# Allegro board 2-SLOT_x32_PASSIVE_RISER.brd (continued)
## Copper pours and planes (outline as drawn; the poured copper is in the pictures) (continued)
GND_A on L2_GND (solid shape): outline of 148 points within -9.4,0.76 159.4,195
GND_A on L4_PWR (solid shape): outline of 148 points within -9.4,0.76 159.4,195
GND_A on L5_PWR (solid shape): outline of 148 points within -9.4,0.76 159.4,195
GND_A on L7_GND (solid shape): outline of 148 points within -9.4,0.76 159.4,195
GND_D on L2_GND: -8.64,337.95 -9.02,338.06 -9.3,338.34 -9.34,338.41 -9.38,338.56 -9.4,338.71 -9.4,348.62 -9.17,349.16 -8.64,349.38 199.14,349.38 199.67,349.16 199.9,348.62 199.9,338.71 199.67,338.17 199.14,337.95 ; 8 cut-outs
GND_D on L4_PWR, L5_PWR: -8.64,337.95 -9.02,338.06 -9.3,338.34 -9.34,338.41 -9.38,338.56 -9.4,338.71 -9.4,348.62 -9.17,349.16 -8.64,349.38 199.14,349.38 199.67,349.16 199.9,348.62 199.9,338.71 199.67,338.17 199.14,337.95
GND_D on L7_GND: -8.64,337.95 -9.02,338.06 -9.3,338.34 -9.34,338.41 -9.38,338.56 -9.4,338.71 -9.4,348.62 -9.17,349.16 -8.64,349.38 199.14,349.38 199.67,349.16 199.9,348.62 199.9,338.71 199.67,338.17 199.14,337.95 ; 8 cut-outs
GND_K on TOP, BOTTOM, L6: -8.64,322.08 -9.1,322.23 -9.37,322.63 -9.38,322.67 -9.39,322.76 -9.4,322.84 -9.4,332.74 -9.39,332.88 -9.35,333.01 -9.31,333.09 -9.21,333.24 -9.08,333.36 -8.98,333.42 -8.93,333.45 -8.88,333.47 -8.82,333.48 -8.76,333.5 -8.7,333.5 -8.64,333.51 199.14,333.51 199.67,333.28 199.9,332.74 199.9,322.84 199.67,322.3 199.14,322.08 ; 4 cut-outs
GND_K on L2_GND: -8.64,322.08 -9.1,322.23 -9.37,322.63 -9.38,322.67 -9.39,322.76 -9.4,322.84 -9.4,332.74 -9.39,332.88 -9.35,333.01 -9.31,333.09 -9.21,333.24 -9.08,333.36 -8.98,333.42 -8.93,333.45 -8.88,333.47 -8.82,333.48 -8.76,333.5 -8.7,333.5 -8.64,333.51 199.14,333.51 199.67,333.28 199.9,332.74 199.9,322.84 199.67,322.3 199.14,322.08 ; 8 cut-outs
GND_K on L3: -8.64,322.08 -9.1,322.23 -9.37,322.63 -9.38,322.67 -9.39,322.76 -9.4,322.84 -9.4,332.74 -9.39,332.88 -9.35,333.01 -9.31,333.09 -9.21,333.24 -9.08,333.36 -8.98,333.42 -8.93,333.45 -8.88,333.47 -8.82,333.48 -8.76,333.5 -8.7,333.5 -8.64,333.51 199.14,333.51 199.67,333.28 199.9,332.74 199.9,322.84 199.67,322.3 199.14,322.08 ; 4 cut-outs
GND_K on L4_PWR, L5_PWR: -8.64,322.08 -9.1,322.23 -9.37,322.63 -9.38,322.67 -9.39,322.76 -9.4,322.84 -9.4,332.74 -9.39,332.88 -9.35,333.01 -9.31,333.09 -9.21,333.24 -9.08,333.36 -8.98,333.42 -8.93,333.45 -8.88,333.47 -8.82,333.48 -8.76,333.5 -8.7,333.5 -8.64,333.51 199.14,333.51 199.67,333.28 199.9,332.74 199.9,322.84 199.67,322.3 199.14,322.08 ; 8 cut-outs
GND_K on L7_GND: -8.64,322.08 -9.1,322.23 -9.37,322.63 -9.38,322.67 -9.39,322.76 -9.4,322.84 -9.4,332.74 -9.39,332.88 -9.35,333.01 -9.31,333.09 -9.21,333.24 -9.08,333.36 -8.98,333.42 -8.93,333.45 -8.88,333.47 -8.82,333.48 -8.76,333.5 -8.7,333.5 -8.64,333.51 199.14,333.51 199.67,333.28 199.9,332.74 199.9,322.84 199.67,322.3 199.14,322.08 ; 8 cut-outs
P3V3 on TOP (solid shape): 112.78,7.24 112.78,4.32 112.41,3.95 112.41,1.05 112.36,1.01 111.09,1.01 111.05,1.05 111.05,4.37 111.38,4.7 111.38,4.7 111.45,4.78 111.45,7.31 111.51,7.37 112.65,7.37
P3V3 on TOP (solid shape): outline of 1532 points within 103.38,11.18 120.14,27.43
P3V3 on BOTTOM (solid shape): 112.78,7.24 112.78,4.32 112.41,3.95 112.41,1.05 112.36,1.01 111.09,1.01 111.05,1.05 111.05,4.37 111.38,4.7 111.38,4.7 111.45,4.78 111.45,7.31 111.51,7.37 112.65,7.37
P3V3 on L3 (solid shape): 112.78,7.24 112.78,4.83 112.65,4.7 111.51,4.7 111.45,4.75 111.45,7.31 111.51,7.37 112.65,7.37
P3V3 on L3 (solid shape): 117.22,27.94 119.89,27.94 120.02,27.81 120.02,26.04 119.89,25.91 114.94,25.91 113.47,27.37 113.28,27.56 111.51,27.56 110.87,26.92 106.43,26.92 106.3,27.05 106.3,28.32 106.49,28.51 116.65,28.51
P3V3 on L3 (solid shape): outline of 105 points within 113.67,12.06 118.36,22.02
P3V3 on L5_PWR (solid shape): outline of 453 points within 101.41,3.8 120.14,30.61
P3V3 on L6 (solid shape): outline of 3899 points within 101.98,3.8 120.14,30.61
P3V3_B on TOP (solid shape): 32.77,81.15 32.77,78.87 32.64,78.74 27.94,78.74 27.81,78.87 27.81,80.1 28.22,80.1 28.23,80.02 28.24,79.94 28.26,79.86 28.29,79.78 28.32,79.7 28.36,79.63 28.41,79.57 28.47,79.5 28.53,79.45 28.59,79.4 28.66,79.36 28.73,79.32 28.81,79.29 28.89,79.27 28.97,79.25 29.05,79.25 29.14,79.25 29.22,79.26 29.3,79.28 29.38,79.3 29.45,79.34 29.52,79.38 29.59,79.42 29.66,79.48 29.71,79.53 29.76,79.6 29.81,79.67 29.85,79.74 29.88,79.82 29.9,79.9 29.92,79.98 29.93,80.06 29.93,80.14 29.92,80.22 29.9,80.3 29.88,80.38 29.85,80.46 29.81,80.53 29.76,80.6 29.71,80.66 29.66,80.72 29.59,80.78 29.52,80.82 29.45,80.86 29.38,80.9 29.3,80.92 29.22,80.94 29.14,80.95 29.05,80.95 28.97,80.95 28.89,80.93 28.81,80.91 28.73,80.88 28.66,80.84 28.59,80.8 28.53,80.75 28.47,80.69 28.41,80.63 28.36,80.57 28.32,80.5 28.29,80.42 28.26,80.34 28.24,80.26 28.23,80.18 28.22,80.1 27.81,80.1 27.81,81.15 28.07,81.41 32.51,81.41
P3V3_B on TOP (solid shape): outline of 1293 points within 103.89,31.37 120.14,47.75
P3V3_B on BOTTOM (solid shape): 32.77,81.15 32.77,78.87 32.64,78.74 27.94,78.74 27.81,78.87 27.81,80.1 28.22,80.1 28.23,80.02 28.24,79.94 28.26,79.86 28.29,79.78 28.32,79.7 28.36,79.63 28.41,79.57 28.47,79.5 28.53,79.45 28.59,79.4 28.66,79.36 28.73,79.32 28.81,79.29 28.89,79.27 28.97,79.25 29.05,79.25 29.14,79.25 29.22,79.26 29.3,79.28 29.38,79.3 29.45,79.34 29.52,79.38 29.59,79.42 29.66,79.48 29.71,79.53 29.76,79.6 29.81,79.67 29.85,79.74 29.88,79.82 29.9,79.9 29.92,79.98 29.93,80.06 29.93,80.14 29.92,80.22 29.9,80.3 29.88,80.38 29.85,80.46 29.81,80.53 29.76,80.6 29.71,80.66 29.66,80.72 29.59,80.78 29.52,80.82 29.45,80.86 29.38,80.9 29.3,80.92 29.22,80.94 29.14,80.95 29.05,80.95 28.97,80.95 28.89,80.93 28.81,80.91 28.73,80.88 28.66,80.84 28.59,80.8 28.53,80.75 28.47,80.69 28.41,80.63 28.36,80.57 28.32,80.5 28.29,80.42 28.26,80.34 28.24,80.26 28.23,80.18 28.22,80.1 27.81,80.1 27.81,81.15 28.07,81.41 32.51,81.41
P3V3_B on L3 (solid shape): 117.22,48.26 119.89,48.26 120.02,48.13 120.02,46.35 119.89,46.23 113.54,46.23 112.39,47.37 109.61,47.37 109.52,47.43 109.53,47.54 109.59,47.65 109.61,47.78 109.23,48.16 108.85,47.78 108.87,47.65 108.94,47.54 108.95,47.43 108.86,47.37 106.43,47.37 106.3,47.5 106.3,48.64 106.49,48.83 116.65,48.83
P3V3_B on L3 (solid shape): 32.77,81.15 32.77,78.87 32.64,78.74 27.94,78.74 27.81,78.87 27.81,80.1 28.22,80.1 28.23,80.02 28.24,79.94 28.26,79.86 28.29,79.78 28.32,79.7 28.36,79.63 28.41,79.57 28.47,79.5 28.53,79.45 28.59,79.4 28.66,79.36 28.73,79.32 28.81,79.29 28.89,79.27 28.97,79.25 29.05,79.25 29.14,79.25 29.22,79.26 29.3,79.28 29.38,79.3 29.45,79.34 29.52,79.38 29.59,79.42 29.66,79.48 29.71,79.53 29.76,79.6 29.81,79.67 29.85,79.74 29.88,79.82 29.9,79.9 29.92,79.98 29.93,80.06 29.93,80.14 29.92,80.22 29.9,80.3 29.88,80.38 29.85,80.46 29.81,80.53 29.76,80.6 29.71,80.66 29.66,80.72 29.59,80.78 29.52,80.82 29.45,80.86 29.38,80.9 29.3,80.92 29.22,80.94 29.14,80.95 29.05,80.95 28.97,80.95 28.89,80.93 28.81,80.91 28.73,80.88 28.66,80.84 28.59,80.8 28.53,80.75 28.47,80.69 28.41,80.63 28.36,80.57 28.32,80.5 28.29,80.42 28.26,80.34 28.24,80.26 28.23,80.18 28.22,80.1 27.81,80.1 27.81,81.15 28.07,81.41 32.51,81.41
P3V3_B on L3 (solid shape): outline of 692 points within 108.58,31.62 119.13,42.42
P3V3_B on L5_PWR (solid shape): 52.85,63.88 108.35,63.88 120.14,52.09 120.14,31.47 119.78,31.11 113.14,31.11 112.78,31.47 112.78,36.22 113.54,36.98 113.54,37.27 113.55,37.28 113.71,37.67 113.77,38.09 113.71,38.51 113.54,38.9 113.54,40.49 110.98,43.05 43.67,43.05 27.81,58.91 27.81,81.05 28.17,81.41 35.33,81.41
P3V3_B on L6 (solid shape): outline of 5520 points within 27.81,7.66 120.14,81.41
P3V3_STBY on TOP (solid shape): 111.19,6.25 111.19,4.77 111.12,4.7 110.65,4.7 110.51,4.84 110.51,5.08 110.5,5.14 110.49,5.2 110.49,5.33 110.36,5.46 110.14,5.46 110.11,5.46 109.86,5.46 109.79,5.53 109.79,6.28 109.86,6.35 111.09,6.35
P3V3_STBY on BOTTOM (solid shape): outline of 9188 points within 75.69,1 120.16,63.88
P3V3_STBY on L3 (solid shape): 111.19,6.25 111.19,4.77 111.12,4.7 110.62,4.7 110.49,4.83 110.49,4.96 110.49,4.97 110.51,5.08 110.49,5.19 110.49,5.2 110.49,5.33 110.36,5.46 109.86,5.46 109.73,5.59 109.73,6.22 109.86,6.35 111.09,6.35
P3V3_STBY on TOP: 111.76,27.05 113.03,27.05 113.16,26.92 113.16,25.78 113.03,25.65 111.76,25.65 111.63,25.78 111.63,26.92
P3V3_STBY on TOP: 111.76,47.37 113.03,47.37 113.16,47.24 113.16,46.1 113.03,45.97 111.76,45.97 111.63,46.1 111.63,47.24
P12V on TOP (solid shape): outline of 984 points within 115.87,1.01 149.23,27.56
P12V on BOTTOM (solid shape): outline of 1425 points within 115.87,1.01 149.23,29.59
P12V on L3 (solid shape): outline of 500 points within 115.95,3.94 149.23,29.59
P12V on L4_PWR (solid shape): 148.98,30.49 148.98,18.48 149.23,18.48 149.23,12.99 148.58,11.4 147,10.75 121.66,10.75 121.34,10.75 121.29,10.7 121.28,10.69 120.63,10.23 120.39,9.48 120.39,3.8 115.95,3.8 115.95,6.63 116.31,6.99 117.58,6.99 118.24,7.64 118.24,9.42 121.01,12.19 123.8,12.19 126.62,15.01 126.62,21.19 122.91,24.89 121.01,24.89 120.65,25.25 120.65,30.25 121.01,30.61 148.87,30.61
P12V on L5_PWR (solid shape): 148.98,30.49 148.98,18.48 149.23,18.48 149.23,12.99 148.58,11.4 147,10.75 121.66,10.75 121.34,10.75 121.29,10.7 121.28,10.69 120.63,10.23 120.39,9.48 120.39,3.8 115.95,3.8 115.95,12.34 117.73,14.12 117.73,15.26 118.75,16.28 118.75,19.54 118.24,20.04 118.24,21.74 120.65,24.15 120.65,30.25 121.01,30.61 148.87,30.61
P12V on L6 (solid shape): outline of 1425 points within 115.95,3.8 149.23,29.59
P12V_B on TOP (solid shape): 32.77,84.68 32.77,82.12 32.57,81.92 27.98,81.92 27.81,82.08 27.81,83.1 28.22,83.1 28.23,83.02 28.24,82.94 28.26,82.86 28.29,82.78 28.32,82.7 28.36,82.63 28.41,82.57 28.47,82.5 28.53,82.45 28.59,82.4 28.66,82.36 28.73,82.32 28.81,82.29 28.89,82.27 28.97,82.25 29.05,82.25 29.14,82.25 29.22,82.26 29.3,82.28 29.38,82.3 29.45,82.34 29.52,82.38 29.59,82.42 29.66,82.48 29.71,82.53 29.76,82.6 29.81,82.67 29.85,82.74 29.88,82.82 29.9,82.9 29.92,82.98 29.93,83.06 29.93,83.14 29.92,83.22 29.9,83.3 29.88,83.38 29.85,83.46 29.81,83.53 29.76,83.6 29.71,83.66 29.66,83.72 29.59,83.78 29.52,83.82 29.45,83.86 29.38,83.9 29.3,83.92 29.22,83.94 29.14,83.95 29.05,83.95 28.97,83.95 28.89,83.93 28.81,83.91 28.73,83.88 28.66,83.84 28.59,83.8 28.53,83.75 28.47,83.69 28.41,83.63 28.36,83.57 28.32,83.5 28.29,83.42 28.26,83.34 28.24,83.26 28.23,83.18 28.22,83.1 27.81,83.1 27.81,84.68 27.98,84.85 32.6,84.85
P12V_B on TOP (solid shape): outline of 621 points within 120.65,31.11 149.23,47.75
P12V_B on BOTTOM (solid shape): outline of 1617 points within 27.81,31.11 149.23,91.24
P12V_B on L3 (solid shape): outline of 1595 points within 27.81,31.11 149.23,91.24
P12V_B on L4_PWR (solid shape): outline of 277 points within 23.88,31.11 149.23,91.24
P12V_B on L5_PWR (solid shape): outline of 277 points within 23.88,31.11 149.23,91.24
P12V_B on L6 (solid shape): outline of 1595 points within 27.81,31.11 149.23,91.24

Small or netless copper shapes (teardrops, artwork), in the pictures only: 2 on TOP

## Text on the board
BOTTOM: 6050A3060301 | A01 SIDE 2
Ref Des/Silkscreen Bottom: DELTA_L_85_L8_2IN | DELTA_L_85_L3_2IN | DELTA_L_85_L8_5IN | DELTA_L_85_L3_5IN | SS2
User.Comments: SM1 | TP1 | SM2 | TP2
TOP: 6050A3060301 | A01 SIDE 1
Ref Des/Silkscreen Top: VENDOR NAME | MTN:01 | DELTA_L_85_L1_2IN | DELTA_L_85_L6_2IN | DeltaL COUPON | 6050A3060301 A01 | DELTA_L_85_L1_5IN | DELTA_L_85_L6_5IN | TDR COUPON | (P1 PCIe 2ABCD) | Riser Slot1 | PWR_Conn | Riser Slot2(P1 PCIe 1ABCD) | SS1
User.13: SP1
User.14: SP2
User.17: FIGURE | FINISHED_SIZE | 10.0 | 16.0 | 24.0 | 28.0 | 41.0 | 42.0 | 157.0 | 220.0 | 93.0 | 122.0 | 125.0 | 159.0 | DRILL CHART: TOP to BOTTOM | ALL UNITS ARE IN MILS | TOLERANCE_DRILL | +3.0/-5.0 | +3.0/-3.0 | +2.0/-2.0 | +5.0/-5.0 | +5.0/-0.0 | +3.0/-0.0 | PLATED | NON-PLATED | QTY | 1783 | 80 | 18 | 328 | 64 | 4 | 3 | 1 | 9
User.18: 6050A3060301 A01
User.19: 6050A3060301 A01
User.20: L1
User.21: L2
User.22: UA1
User.23: UA2
User.24: CD1
User.25: CD2
User.35: PF
User.36: L3
User.37: L4
User.38: L5
User.39: L6
User.44: L7
User.45: L8
